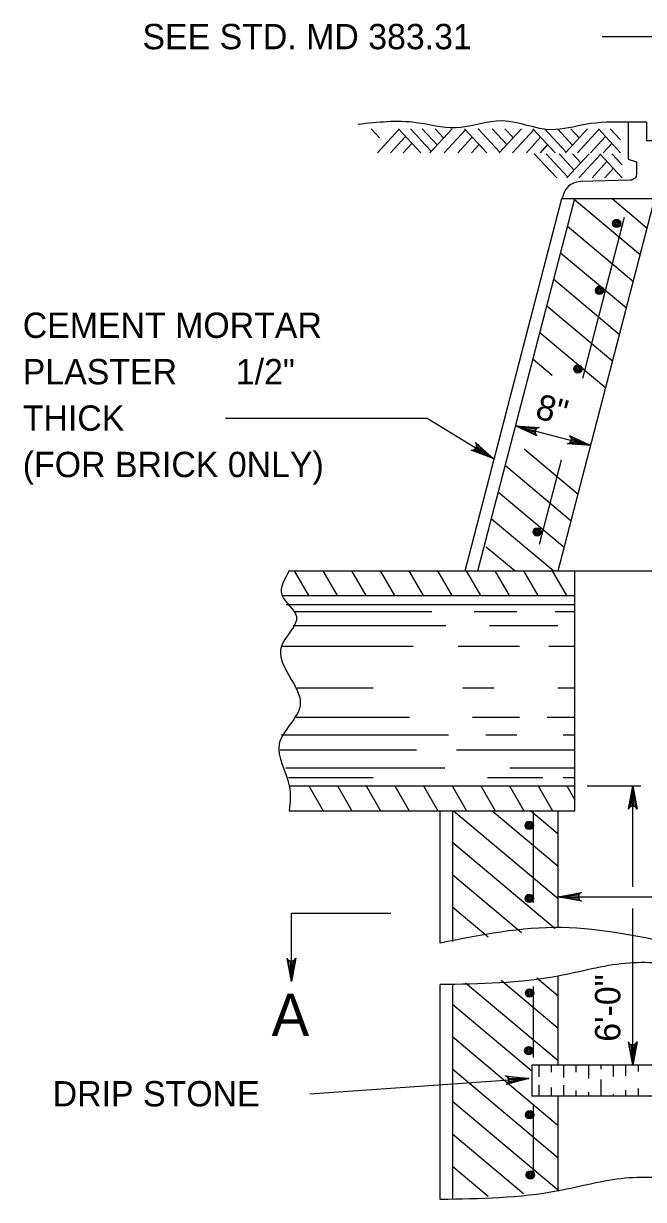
# Model space of a CAD drawing. Extents: x 0.2 to 7.1, y 1.2 to 11.2.
# Drawn here: x 0.258 to 1.727, y 5.561 to 8.348 of the extents above; entities that cross this region are included whole.
import ezdxf

# ---------------------------------------------------------------- set-up
doc = ezdxf.new("R2010")
doc.units = 0
for name, color, linetype in [('DETL-DIMS', 7, 'Continuous'), ('DETL-LINE', 7, 'Continuous'), ('DETL-NOTE', 7, 'Continuous'), ('DETL-PATT', 7, 'Continuous')]:
    doc.layers.add(name, color=color, linetype=linetype)

msp = doc.modelspace()

# ---------------------------------------------------------------- linework, layer by layer
at = {"layer": 'DETL-DIMS'}
for p, q in [((1.6294, 8.3172), (1.8102, 8.3172)), ((0.7363, 7.4129), (1.2147, 7.4129)), ((1.2147, 7.4129), (1.3707, 7.3172)), ((1.424, 7.3942), (1.6022, 7.3479)), ((1.5937, 6.541), (1.7209, 6.541)), ((1.7015, 6.3014), (1.7015, 6.541)), ((1.525, 6.2779), (2.3878, 6.2779)), ((1.7015, 5.879), (1.7015, 6.2504)), ((0.8927, 6.0775), (0.8927, 6.2393)), ((0.8927, 6.2393), (1.128, 6.2393)), ((0.9365, 5.8112), (1.4554, 5.8471))]:
    msp.add_line(p, q, dxfattribs=at)
for points in [[(1.424, 7.3942), (1.4797, 7.3904), (1.4749, 7.3886), (1.4718, 7.3856), (1.4703, 7.3822), (1.47, 7.3785), (1.4712, 7.3744), (1.4745, 7.3705), (1.424, 7.3942), (1.4712, 7.3744), (1.47, 7.3785), (1.424, 7.3942), (1.4703, 7.3822), (1.4718, 7.3856), (1.424, 7.3942), (1.4749, 7.3886)], [(1.6022, 7.3479), (1.5466, 7.3518), (1.5514, 7.3535), (1.5544, 7.3565), (1.556, 7.3599), (1.5563, 7.3637), (1.5551, 7.3678), (1.5517, 7.3717), (1.6022, 7.3479), (1.5551, 7.3678), (1.5563, 7.3637), (1.6022, 7.3479), (1.556, 7.3599), (1.5544, 7.3565), (1.6022, 7.3479), (1.5514, 7.3535)], [(1.3707, 7.3172), (1.3186, 7.3371), (1.3237, 7.3374), (1.3275, 7.3394), (1.3299, 7.3422), (1.3313, 7.3456), (1.3314, 7.3499), (1.3293, 7.3546), (1.3707, 7.3172), (1.3314, 7.3499), (1.3313, 7.3456), (1.3707, 7.3172), (1.3299, 7.3422), (1.3275, 7.3394), (1.3707, 7.3172), (1.3237, 7.3374)], [(1.7015, 6.541), (1.7118, 6.4861), (1.7088, 6.4904), (1.7052, 6.4925), (1.7015, 6.4932), (1.6978, 6.4925), (1.6941, 6.4904), (1.6912, 6.4861), (1.7015, 6.541), (1.6941, 6.4904), (1.6978, 6.4925), (1.7015, 6.541), (1.7015, 6.4932), (1.7052, 6.4925), (1.7015, 6.541), (1.7088, 6.4904)], [(1.525, 6.2779), (1.5799, 6.2882), (1.5756, 6.2853), (1.5734, 6.2816), (1.5728, 6.2779), (1.5734, 6.2743), (1.5756, 6.2706), (1.5799, 6.2677), (1.525, 6.2779), (1.5756, 6.2706), (1.5734, 6.2743), (1.525, 6.2779), (1.5728, 6.2779), (1.5734, 6.2816), (1.525, 6.2779), (1.5756, 6.2853)], [(0.8927, 6.0775), (0.8824, 6.1324), (0.8853, 6.1281), (0.889, 6.126), (0.8927, 6.1253), (0.8963, 6.126), (0.9, 6.1281), (0.903, 6.1324), (0.8927, 6.0775), (0.9, 6.1281), (0.8963, 6.126), (0.8927, 6.0775), (0.8927, 6.1253), (0.889, 6.126), (0.8927, 6.0775), (0.8853, 6.1281)], [(1.7015, 5.879), (1.6912, 5.9339), (1.6941, 5.9297), (1.6978, 5.9275), (1.7015, 5.9268), (1.7052, 5.9275), (1.7088, 5.9297), (1.7118, 5.9339), (1.7015, 5.879), (1.7088, 5.9297), (1.7052, 5.9275), (1.7015, 5.879), (1.7015, 5.9268), (1.6978, 5.9275), (1.7015, 5.879), (1.6941, 5.9297)], [(1.4554, 5.8471), (1.4014, 5.8331), (1.4054, 5.8363), (1.4073, 5.8401), (1.4077, 5.8438), (1.4068, 5.8474), (1.4044, 5.851), (1.4, 5.8536), (1.4554, 5.8471), (1.4044, 5.851), (1.4068, 5.8474), (1.4554, 5.8471), (1.4077, 5.8438), (1.4073, 5.8401), (1.4554, 5.8471), (1.4054, 5.8363)]]:
    msp.add_lwpolyline(points, dxfattribs=at)
at = {"layer": 'DETL-LINE'}
for p, q in [((1.3044, 7.0508), (1.5336, 7.9331)), ((1.3348, 7.0508), (1.564, 7.9331)), ((1.525, 7.0508), (1.7542, 7.9331)), ((1.5336, 7.9331), (2.3572, 7.9331)), ((1.5829, 7.5074), (1.682, 7.8889)), ((1.4806, 7.1138), (1.5326, 7.3141)), ((0.8878, 7.0508), (1.5642, 7.0508)), ((1.5642, 6.992), (1.5642, 7.0508)), ((1.5642, 7.0508), (2.3878, 7.0508)), ((0.8698, 6.992), (1.5642, 6.992)), ((1.5642, 6.541), (1.5642, 6.992)), ((0.8878, 6.541), (1.5642, 6.541)), ((1.5642, 6.4822), (1.5642, 6.541)), ((0.8878, 6.4822), (1.5642, 6.4822)), ((1.2456, 6.1684), (1.2456, 6.4822)), ((1.275, 6.1722), (1.275, 6.4822)), ((1.4662, 6.2634), (1.4662, 6.4822)), ((1.525, 6.2042), (1.525, 6.4822)), ((1.525, 5.8788), (1.525, 6.09)), ((1.2456, 5.5606), (1.2456, 6.0699)), ((1.275, 5.5627), (1.275, 6.072)), ((1.4662, 5.897), (1.4662, 6.0656)), ((1.9575, 5.879), (1.4624, 5.879)), ((1.4624, 5.879), (1.4624, 5.8055)), ((1.9575, 5.8055), (1.4624, 5.8055)), ((1.525, 5.5807), (1.525, 5.8055)), ((1.4662, 5.6149), (1.4662, 5.7853))]:
    msp.add_line(p, q, dxfattribs=at)
msp.add_lwpolyline([(1.6905, 8.1145), (1.6905, 8.0263), (1.7101, 8.0206), (1.7101, 7.9915), (1.7094, 7.9858), (1.7073, 7.9827), (1.7053, 7.981), (1.7028, 7.9789), (1.6994, 7.9771), (1.6958, 7.9768), (1.5775, 7.9733), (1.5693, 7.9723), (1.5614, 7.9695), (1.5551, 7.9667), (1.5496, 7.9626), (1.5444, 7.9574), (1.5409, 7.9518), (1.5371, 7.9435), (1.5357, 7.9379), (1.5336, 7.9331), (1.7542, 7.9331), (1.7542, 8.0704), (1.7346, 8.0704), (1.7346, 8.1145)], close=True, dxfattribs=at)
for centre, radius in [((1.6633, 7.8742), 0.0098), ((1.6633, 7.8742), 0.00735), ((1.6633, 7.8742), 0.0049), ((1.6633, 7.8742), 0.00245), ((1.6228, 7.7155), 0.0098), ((1.6228, 7.7155), 0.00735), ((1.6228, 7.7155), 0.0049), ((1.6228, 7.7155), 0.00245), ((1.5716, 7.5293), 0.0098), ((1.5716, 7.5293), 0.00735), ((1.5716, 7.5293), 0.0049), ((1.5716, 7.5293), 0.00245), ((1.4751, 7.143), 0.0098), ((1.4751, 7.143), 0.00735), ((1.4751, 7.143), 0.0049), ((1.4751, 7.143), 0.00245), ((1.4562, 6.4472), 0.0098), ((1.4562, 6.4472), 0.00735), ((1.4562, 6.4472), 0.0049), ((1.4562, 6.4472), 0.00245), ((1.4562, 6.2742), 0.0098), ((1.4562, 6.2742), 0.00735), ((1.4562, 6.2742), 0.0049), ((1.4562, 6.2742), 0.00245), ((1.457, 6.05), 0.0098), ((1.457, 6.05), 0.00735), ((1.457, 6.05), 0.0049), ((1.457, 6.05), 0.00245), ((1.4551, 5.9134), 0.0098), ((1.4551, 5.9134), 0.00735), ((1.4551, 5.9134), 0.0049), ((1.4551, 5.9134), 0.00245), ((1.457, 5.7613), 0.0098), ((1.457, 5.7613), 0.00735), ((1.457, 5.7613), 0.0049), ((1.457, 5.7613), 0.00245), ((1.459, 5.6188), 0.0098), ((1.459, 5.6188), 0.00735), ((1.459, 5.6188), 0.0049), ((1.459, 5.6188), 0.00245)]:
    msp.add_circle(centre, radius, dxfattribs=at)
for points in [[(1.6905, 8.1145), (1.589, 8.1089), (1.5098, 8.0963), (1.393, 8.1172), (1.2804, 8.1005), (1.1886, 8.113), (1.051, 8.1089)], [(0.8878, 7.0508), (0.8702, 6.9938), (0.9047, 6.9422), (0.869, 6.8722), (0.9136, 6.7335), (0.864, 6.6406), (0.8878, 6.541), (0.8878, 6.4822)], [(2.6672, 6.1684), (2.5405, 6.1525), (2.386, 6.1946), (2.112, 6.149), (1.5326, 6.2052), (1.2456, 6.1684)], [(2.6672, 6.09), (2.5361, 6.0779), (2.2058, 6.096), (1.8352, 6.1162), (1.6841, 6.1202), (1.525, 6.09), (1.2456, 6.0699)], [(2.6672, 5.5807), (2.5361, 5.5686), (2.2058, 5.5867), (1.8352, 5.6069), (1.6841, 5.6109), (1.525, 5.5807), (1.2456, 5.5606)]]:
    msp.add_spline(points, degree=3, dxfattribs=at)
at = {"layer": 'DETL-PATT'}
for p, q in [((1.1012, 8.077), (1.0814, 8.0986)), ((1.0966, 8.0417), (1.1475, 8.0968)), ((1.1991, 8.0417), (1.1464, 8.0986)), ((1.1991, 8.0721), (1.1747, 8.0986)), ((1.238, 8.0604), (1.2023, 8.0986)), ((1.2207, 8.0417), (1.2734, 8.0986)), ((1.2532, 8.0769), (1.2334, 8.0986)), ((1.2546, 8.0417), (1.3052, 8.096)), ((1.3557, 8.0417), (1.3027, 8.0986)), ((1.3868, 8.0433), (1.3356, 8.0986)), ((1.4031, 8.061), (1.3685, 8.0986)), ((1.3854, 8.0417), (1.4381, 8.0986)), ((1.4179, 8.0776), (1.3988, 8.0986)), ((1.4169, 8.0417), (1.4671, 8.0958)), ((1.518, 8.0417), (1.4646, 8.0986)), ((1.5438, 8.0435), (1.4925, 8.0986)), ((1.559, 8.0599), (1.5233, 8.0986)), ((1.542, 8.0417), (1.5946, 8.0988)), ((1.5749, 8.077), (1.5551, 8.0986)), ((1.5703, 8.0417), (1.6212, 8.0968)), ((1.6728, 8.0417), (1.6201, 8.0986)), ((1.6728, 8.0721), (1.6484, 8.0986)), ((1.1277, 8.0417), (1.163, 8.0804)), ((1.1577, 8.0417), (1.1782, 8.0641)), ((1.2239, 8.0452), (1.1988, 8.0721)), ((1.2872, 8.0417), (1.3214, 8.0786)), ((1.3193, 8.0417), (1.3373, 8.0613)), ((1.4494, 8.0417), (1.4833, 8.0786)), ((1.4826, 8.0417), (1.4999, 8.0608)), ((1.6014, 8.0417), (1.6367, 8.0804)), ((1.6314, 8.0417), (1.6519, 8.0641)), ((1.2022, 8.0417), (1.2022, 8.0417)), ((1.5217, 7.9825), (1.4683, 8.0394)), ((1.5475, 7.9842), (1.4962, 8.0394)), ((1.5627, 8.0007), (1.527, 8.0394)), ((1.5457, 7.9825), (1.5983, 8.0395)), ((1.5786, 8.0178), (1.5588, 8.0394)), ((1.574, 7.9825), (1.6249, 8.0376)), ((1.6765, 7.9825), (1.6238, 8.0394)), ((1.6765, 8.0128), (1.6521, 8.0394)), ((1.6051, 7.9825), (1.6404, 8.0212)), ((1.6351, 7.9825), (1.6556, 8.0049)), ((1.5635, 7.9309), (1.7196, 7.7999)), ((1.6524, 7.9331), (1.736, 7.8629)), ((1.5471, 7.8679), (1.7032, 7.7369)), ((1.5307, 7.8048), (1.6869, 7.6738)), ((1.5143, 7.7418), (1.6705, 7.6108)), ((1.498, 7.6788), (1.6541, 7.5477)), ((1.4816, 7.6157), (1.6377, 7.4847)), ((1.4652, 7.5527), (1.5102, 7.5149)), ((1.444, 7.34), (1.5722, 7.2325)), ((1.3997, 7.3005), (1.5558, 7.1694)), ((1.3833, 7.2374), (1.5395, 7.1064)), ((1.3669, 7.1744), (1.5142, 7.0508)), ((1.3545, 7.108), (1.4227, 7.0508)), ((0.8994, 7.0508), (0.9334, 6.992)), ((0.9673, 7.0508), (1.0013, 6.992)), ((1.0352, 7.0508), (1.0692, 6.992)), ((1.1032, 7.0508), (1.1371, 6.992)), ((1.1711, 7.0508), (1.2051, 6.992)), ((1.239, 7.0508), (1.273, 6.992)), ((1.3069, 7.0508), (1.3409, 6.992)), ((1.3749, 7.0508), (1.4088, 6.992)), ((1.4428, 7.0508), (1.4768, 6.992)), ((1.5107, 7.0508), (1.5447, 6.992)), ((0.8806, 6.9713), (1.5642, 6.9713)), ((0.8988, 6.9545), (1.2251, 6.9545)), ((1.3261, 6.9545), (1.427, 6.9545)), ((1.5175, 6.9545), (1.5642, 6.9545)), ((0.8968, 6.9208), (1.2587, 6.9208)), ((1.3618, 6.9208), (1.5238, 6.9208)), ((0.869, 6.8724), (1.1809, 6.8724)), ((1.2882, 6.8724), (1.4334, 6.8724)), ((1.5028, 6.8724), (1.5642, 6.8724)), ((0.9063, 6.7735), (1.0862, 6.7735)), ((1.2987, 6.7735), (1.3723, 6.7735)), ((1.5238, 6.7735), (1.5642, 6.7735)), ((0.8998, 6.704), (1.1725, 6.704)), ((1.3218, 6.704), (1.4334, 6.704)), ((1.4986, 6.704), (1.5642, 6.704)), ((0.8688, 6.6619), (1.265, 6.6619)), ((1.3534, 6.6619), (1.427, 6.6619)), ((1.5364, 6.6619), (1.5642, 6.6619)), ((0.8662, 6.6261), (1.1893, 6.6261)), ((1.284, 6.6261), (1.5642, 6.6261)), ((0.8793, 6.584), (1.2566, 6.584)), ((1.4102, 6.584), (1.5642, 6.584)), ((0.8856, 6.5608), (1.0862, 6.5608)), ((1.3576, 6.5608), (1.4881, 6.5608)), ((1.5364, 6.5608), (1.5642, 6.5608)), ((0.9338, 6.541), (0.9678, 6.4822)), ((1.0017, 6.541), (1.0357, 6.4822)), ((1.0697, 6.541), (1.1036, 6.4822)), ((1.1376, 6.541), (1.1715, 6.4822)), ((1.2055, 6.541), (1.2395, 6.4822)), ((1.2734, 6.541), (1.3074, 6.4822)), ((1.3413, 6.541), (1.3753, 6.4822)), ((1.4093, 6.541), (1.4432, 6.4822)), ((1.4772, 6.541), (1.5112, 6.4822)), ((1.5451, 6.541), (1.5642, 6.5079)), ((1.2768, 6.4822), (1.525, 6.2738)), ((1.3683, 6.4822), (1.525, 6.3506)), ((1.4598, 6.4822), (1.525, 6.4274)), ((1.275, 6.4068), (1.5176, 6.2033)), ((1.275, 6.33), (1.4382, 6.1931)), ((1.275, 6.2532), (1.3588, 6.1829)), ((1.3897, 6.0803), (1.525, 5.9667)), ((1.474, 6.0863), (1.525, 6.0435)), ((1.3054, 6.0742), (1.525, 5.8899)), ((1.275, 6.0229), (1.4624, 5.8657)), ((1.275, 5.9461), (1.525, 5.7363)), ((1.275, 5.8693), (1.525, 5.6595)), ((1.4787, 5.879), (1.4787, 5.8511)), ((1.5081, 5.879), (1.5081, 5.8621)), ((1.5375, 5.879), (1.5375, 5.8501)), ((1.5669, 5.879), (1.5669, 5.8621)), ((1.5963, 5.879), (1.5963, 5.8474)), ((1.6257, 5.879), (1.6257, 5.8695)), ((1.6551, 5.879), (1.6551, 5.852)), ((1.6846, 5.879), (1.6846, 5.8538)), ((1.714, 5.879), (1.714, 5.864)), ((1.4787, 5.8326), (1.4787, 5.8055)), ((1.5081, 5.8261), (1.5081, 5.8055)), ((1.5375, 5.8317), (1.5375, 5.8055)), ((1.6257, 5.8446), (1.6257, 5.8055)), ((1.5669, 5.8187), (1.5669, 5.8055)), ((1.5963, 5.815), (1.5963, 5.8055)), ((1.6551, 5.8104), (1.6551, 5.8055)), ((1.6846, 5.8196), (1.6846, 5.8055)), ((1.714, 5.8233), (1.714, 5.8055)), ((1.275, 5.7925), (1.5273, 5.5809)), ((1.275, 5.7157), (1.443, 5.5748)), ((1.275, 5.6389), (1.3587, 5.5687))]:
    msp.add_line(p, q, dxfattribs=at)

# ---------------------------------------------------------------- texts
at = {"layer": 'DETL-NOTE'}
for s, height, p in [('SEE STD. MD 383.31', 0.06, (0.5398, 8.2872)), ('CEMENT MORTAR', 0.06, (0.2562, 7.6029)), ('1/2"', 0.06, (0.761, 7.4929)), ('PLASTER', 0.06, (0.2562, 7.4929)), ('THICK', 0.06, (0.2562, 7.3829)), ('(FOR BRICK 0NLY)', 0.06, (0.2562, 7.2729)), ('A', 0.1, (0.8457, 5.9481)), ('DRIP STONE', 0.06, (0.3271, 5.7812))]:
    msp.add_text(s, height=height, dxfattribs=at).set_placement(p)
for s, rotation, p in [('8"', 345.4382, (1.4677, 7.4133)), ('6\'-0"', 90, (1.6721, 5.9345))]:
    msp.add_text(s, height=0.06, rotation=rotation, dxfattribs=at).set_placement(p)

doc.saveas('drawing.dxf')
